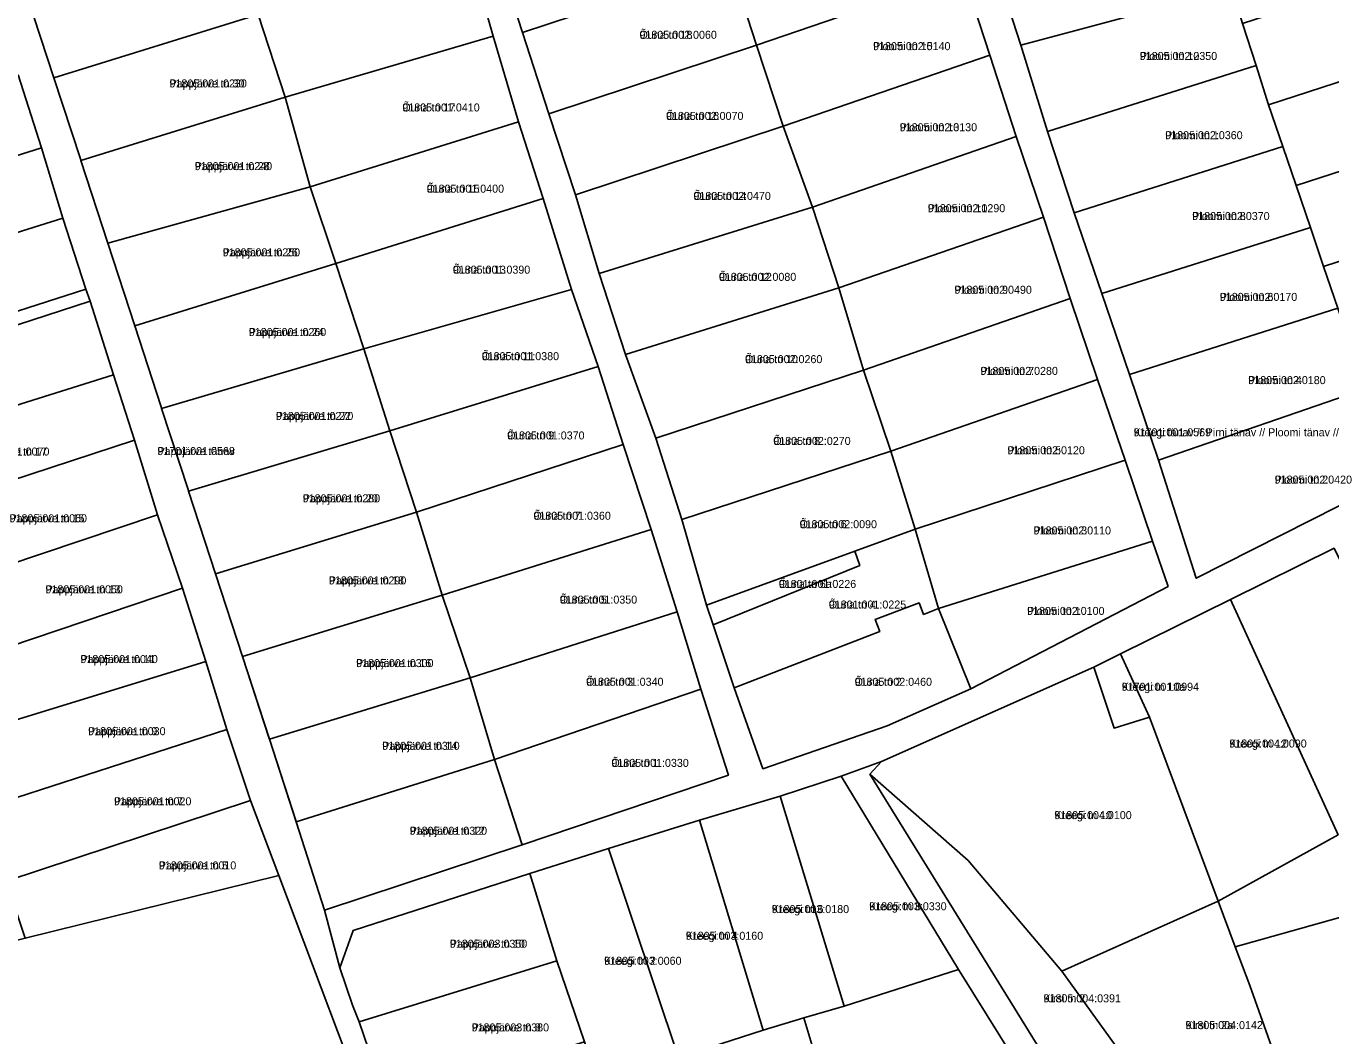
# Model space of a CAD drawing. Extents: x 655954 to 711923, y 6395079 to 6429745.
# Drawn here: x 680310.1 to 680554.7, y 6412291.4 to 6412480.8 of the extents above; entities that cross this region are included whole.
import ezdxf

# ---------------------------------------------------------------- set-up
doc = ezdxf.new("R2010")
doc.units = 0
for name, color, linetype in [('L_AADRESS', 7, 'Continuous'), ('PIIR', 7, 'Continuous'), ('TUNNUS', 7, 'Continuous')]:
    doc.layers.add(name, color=color, linetype=linetype)

msp = doc.modelspace()

# ---------------------------------------------------------------- linework, layer by layer
at = {"layer": 'PIIR'}
for points in [[(680398.24, 6412494.78), (680437.15, 6412507.67), (680441.72, 6412493.55), (680442.08, 6412492.44), (680403.17, 6412479.55)], [(680480.87, 6412505.74), (680485.79, 6412490.52), (680447.01, 6412477.21), (680442.08, 6412492.44)], [(680496.53, 6412477.2), (680491.36, 6412493.27), (680513.5, 6412500.46), (680514.14, 6412498.52), (680530.99, 6412503.84), (680533.46, 6412496.2), (680536.07, 6412487.8)], [(680348.59, 6412498.45), (680353.64, 6412482.95), (680315.35, 6412471.08), (680310.3, 6412486.58)], [(680353.64, 6412482.95), (680393.05, 6412495.15), (680397.69, 6412478.89), (680358.69, 6412467.45)], [(680403.17, 6412479.55), (680442.08, 6412492.44), (680447.01, 6412477.21), (680408.11, 6412464.32)], [(680543, 6412466), (680540.64, 6412473.35), (680538.11, 6412481.23), (680578.1, 6412494.24), (680582.92, 6412478.99)], [(680485.79, 6412490.52), (680490.73, 6412475.29), (680452.04, 6412461.99), (680447.01, 6412477.21)], [(680501.58, 6412461.01), (680496.53, 6412477.2), (680536.07, 6412487.8), (680538.11, 6412481.23), (680540.64, 6412473.35)], [(680353.64, 6412482.95), (680358.69, 6412467.45), (680320.4, 6412455.58), (680320.31, 6412455.85), (680315.35, 6412471.08)], [(680358.69, 6412467.45), (680397.69, 6412478.89), (680402.42, 6412462.83), (680363.38, 6412450.63)], [(680548.14, 6412450.85), (680545.66, 6412458.17), (680543, 6412466), (680582.92, 6412478.99), (680588.07, 6412463.84)], [(680408.11, 6412464.32), (680447.01, 6412477.21), (680452.04, 6412461.99), (680413.12, 6412449.13)], [(680490.73, 6412475.29), (680495.66, 6412460.07), (680457.49, 6412446.82), (680452.04, 6412461.99)], [(680506.55, 6412445.76), (680501.58, 6412461.01), (680540.64, 6412473.35), (680543, 6412466), (680545.66, 6412458.17)], [(680308.64, 6412471.62), (680313.01, 6412457.95), (680245.07, 6412436.41), (680240.87, 6412450.14)], [(680358.69, 6412467.45), (680363.38, 6412450.63), (680325.45, 6412440.08), (680320.4, 6412455.58)], [(680363.38, 6412450.63), (680402.42, 6412462.83), (680407.03, 6412448.42), (680368.19, 6412436.23)], [(680553.29, 6412435.7), (680550.82, 6412443.02), (680548.14, 6412450.85), (680588.07, 6412463.84), (680593.23, 6412448.68)], [(680413.12, 6412449.13), (680452.04, 6412461.99), (680457.49, 6412446.82), (680417.51, 6412434.36)], [(680313.01, 6412457.95), (680317.03, 6412444.78), (680248.37, 6412423.19), (680245.07, 6412436.41)], [(680495.66, 6412460.07), (680500.79, 6412444.91), (680462.42, 6412431.66), (680457.49, 6412446.82)], [(680511.72, 6412430.62), (680506.55, 6412445.76), (680545.66, 6412458.17), (680548.14, 6412450.85), (680550.82, 6412443.02)], [(680363.38, 6412450.63), (680368.19, 6412436.23), (680330.5, 6412424.58), (680325.45, 6412440.08)], [(680368.19, 6412436.23), (680407.03, 6412448.42), (680412.36, 6412431.39), (680373.44, 6412420.27)], [(680558.48, 6412420.56), (680555.97, 6412427.89), (680553.29, 6412435.7), (680593.23, 6412448.68), (680598.48, 6412433.57)], [(680422.47, 6412419.18), (680417.51, 6412434.36), (680457.49, 6412446.82), (680462.42, 6412431.66)], [(680317.03, 6412444.78), (680321.34, 6412431.42), (680261.14, 6412412.06), (680259.66, 6412416.51), (680250.78, 6412413.69), (680248.37, 6412423.19)], [(680505.8, 6412429.67), (680467.07, 6412416.25), (680462.42, 6412431.66), (680500.79, 6412444.91)], [(680516.89, 6412415.47), (680511.72, 6412430.62), (680550.82, 6412443.02), (680553.29, 6412435.7), (680555.97, 6412427.89)], [(680368.19, 6412436.23), (680373.44, 6412420.27), (680335.54, 6412409.08), (680335.45, 6412409.36), (680330.5, 6412424.58)], [(680322.13, 6412429.18), (680262.23, 6412409.71), (680264.29, 6412402.3), (680254.55, 6412399.61), (680250.78, 6412413.69), (680259.66, 6412416.51), (680261.14, 6412412.06), (680321.34, 6412431.42)], [(680378.32, 6412404.88), (680373.44, 6412420.27), (680412.36, 6412431.39), (680417.34, 6412416.92)], [(680422.47, 6412419.18), (680462.42, 6412431.66), (680467.07, 6412416.25), (680428.13, 6412403.48)], [(680264.29, 6412402.3), (680262.23, 6412409.71), (680322.13, 6412429.18), (680326.55, 6412415.35), (680266.62, 6412396.55)], [(680505.8, 6412429.67), (680510.93, 6412414.51), (680472.2, 6412401.06), (680467.07, 6412416.25)], [(680522.35, 6412399.39), (680516.89, 6412415.47), (680555.97, 6412427.89), (680558.48, 6412420.56), (680561.17, 6412412.73)], [(680373.44, 6412420.27), (680378.32, 6412404.88), (680340.59, 6412393.58), (680340.5, 6412393.86), (680335.54, 6412409.08)], [(680378.32, 6412404.88), (680417.34, 6412416.92), (680422.06, 6412402.33), (680383.31, 6412389.61)], [(680428.13, 6412403.48), (680467.07, 6412416.25), (680472.2, 6412401.06), (680433, 6412388.24)], [(680266.62, 6412396.55), (680326.55, 6412415.35), (680330.46, 6412403.15), (680275.58, 6412385.15)], [(680510.93, 6412414.51), (680516.09, 6412399.37), (680476.78, 6412386.46), (680472.2, 6412401.06)], [(680529.44, 6412377.25), (680522.35, 6412399.39), (680561.17, 6412412.73), (680566.82, 6412396.17)], [(680378.32, 6412404.88), (680383.31, 6412389.61), (680345.64, 6412378.08), (680340.59, 6412393.58)], [(680275.58, 6412385.15), (680330.46, 6412403.15), (680334.76, 6412389.13), (680284.72, 6412372.33)], [(680383.31, 6412389.61), (680422.06, 6412402.33), (680427.3, 6412386.4), (680388.13, 6412374.1)], [(680476.78, 6412386.46), (680465.44, 6412382.34), (680437.63, 6412372.2), (680433, 6412388.24), (680472.2, 6412401.06)], [(680516.09, 6412399.37), (680521.25, 6412384.22), (680481.14, 6412371.55), (680476.78, 6412386.46)], [(680383.31, 6412389.61), (680388.13, 6412374.1), (680350.69, 6412362.58), (680345.64, 6412378.08)], [(680284.72, 6412372.33), (680334.76, 6412389.13), (680339.43, 6412375.37), (680292.97, 6412359.71)], [(680388.13, 6412374.1), (680427.3, 6412386.4), (680432.13, 6412370.92), (680393.34, 6412358.58)], [(680465.44, 6412382.34), (680476.78, 6412386.46), (680481.14, 6412371.55), (680478.32, 6412370.45), (680477.5, 6412372.62), (680469.28, 6412369.52), (680470.13, 6412367.27), (680442.85, 6412356.68), (680438.87, 6412368.51), (680466.36, 6412379.66)], [(680437.63, 6412372.2), (680465.44, 6412382.34), (680466.36, 6412379.66), (680438.87, 6412368.51)], [(680521.25, 6412384.22), (680524.14, 6412375.7), (680487.16, 6412356.51), (680481.14, 6412371.55)], [(680556.01, 6412329.17), (680535.87, 6412373.26), (680555.27, 6412382.86), (680558.9, 6412375.47), (680562.02, 6412369.46), (680573.96, 6412339.16), (680581.04, 6412320.56), (680536.7, 6412308.12), (680533.53, 6412316.71)], [(680292.97, 6412359.71), (680339.43, 6412375.37), (680343.83, 6412361.63), (680297.31, 6412347.3)], [(680388.13, 6412374.1), (680393.34, 6412358.58), (680355.73, 6412347.08), (680355.64, 6412347.36), (680350.69, 6412362.58)], [(680471.5, 6412349.58), (680448.23, 6412341.54), (680442.85, 6412356.68), (680470.13, 6412367.27), (680469.28, 6412369.52), (680477.5, 6412372.62), (680478.32, 6412370.45), (680481.14, 6412371.55), (680487.16, 6412356.51)], [(680520.65, 6412351.23), (680515.26, 6412363.1), (680535.87, 6412373.26), (680556.01, 6412329.17), (680533.53, 6412316.71)], [(680393.34, 6412358.58), (680432.13, 6412370.92), (680436.59, 6412356.48), (680397.95, 6412343.26)], [(680520.65, 6412351.23), (680514.02, 6412349.16), (680510.24, 6412360.6), (680515.26, 6412363.1)], [(680297.31, 6412347.3), (680343.83, 6412361.63), (680347.79, 6412348.87), (680301.78, 6412334.02)], [(680486.71, 6412324.31), (680468.27, 6412340.52), (680470.47, 6412342.9), (680510.24, 6412360.6), (680514.02, 6412349.16), (680520.65, 6412351.23), (680533.53, 6412316.71), (680504.21, 6412303.58)], [(680393.34, 6412358.58), (680397.95, 6412343.26), (680360.78, 6412331.58), (680360.69, 6412331.86), (680355.73, 6412347.08)], [(680397.95, 6412343.26), (680436.59, 6412356.48), (680441.76, 6412340.34), (680403.1, 6412327.28)], [(680301.78, 6412334.02), (680347.79, 6412348.87), (680352.17, 6412335.58), (680306.39, 6412320.48)], [(680397.95, 6412343.26), (680403.1, 6412327.28), (680366.09, 6412315.05), (680360.78, 6412331.58)], [(680468.27, 6412340.52), (680486.71, 6412324.31), (680504.21, 6412303.58), (680533.37, 6412263.23), (680520.07, 6412256.74)], [(680462.89, 6412340.13), (680484.86, 6412303.92), (680463.42, 6412297.01), (680451.44, 6412336.37)], [(680306.39, 6412320.48), (680352.17, 6412335.58), (680357.48, 6412321.49), (680309.99, 6412309.75)], [(680436.31, 6412331.9), (680451.44, 6412336.37), (680463.42, 6412297.01), (680455.87, 6412294.86), (680448.28, 6412292.55)], [(680419.26, 6412326.61), (680436.31, 6412331.9), (680448.28, 6412292.55), (680432.38, 6412287.38)], [(680417.09, 6412282.78), (680414.79, 6412290.36), (680409.59, 6412305.53), (680404.56, 6412321.9), (680419.26, 6412326.61), (680432.38, 6412287.38)], [(680270.91, 6412285.97), (680269.56, 6412291.77), (680268.21, 6412300.15), (680272.04, 6412300.46), (680309.99, 6412309.75), (680357.48, 6412321.49), (680370.12, 6412288.02), (680379.49, 6412257.67), (680371.24, 6412239.08), (680328.42, 6412244.77), (680267.41, 6412253.09), (680266.95, 6412257.92), (680268.29, 6412258.95), (680268.5, 6412260.8), (680268.26, 6412264.21), (680268.94, 6412267.94), (680271.87, 6412272.08), (680272.87, 6412275.64), (680272.53, 6412278.95)], [(680368.93, 6412304.18), (680371.42, 6412311.21), (680404.56, 6412321.9), (680409.59, 6412305.53), (680372.55, 6412294.06), (680371.34, 6412297.19)], [(680618.32, 6412308.62), (680620.58, 6412307.34), (680623.03, 6412290.2), (680620.29, 6412289.89), (680608.75, 6412288.56), (680550.62, 6412269.6), (680539.47, 6412300.88), (680536.7, 6412308.12), (680581.04, 6412320.56), (680588.15, 6412306.97), (680590.63, 6412307.28)], [(680504.21, 6412303.58), (680533.53, 6412316.71), (680536.7, 6412308.12), (680539.47, 6412300.88), (680550.62, 6412269.6), (680545.58, 6412269.1), (680533.37, 6412263.23)], [(680377.69, 6412279.06), (680372.55, 6412294.06), (680409.59, 6412305.53), (680414.79, 6412290.36)], [(680498.01, 6412282.81), (680462.72, 6412272.18), (680460.59, 6412279.24), (680455.87, 6412294.86), (680463.42, 6412297.01), (680484.86, 6412303.92)], [(680420.82, 6412275.45), (680419.47, 6412275.06), (680417.09, 6412282.78), (680432.38, 6412287.38), (680448.28, 6412292.55), (680455.87, 6412294.86), (680460.59, 6412279.24), (680423.36, 6412267.88)]]:
    msp.add_lwpolyline(points, close=True, dxfattribs=at)
for points in [[(680305.26, 6412502.08), (680310.3, 6412486.58), (680315.35, 6412471.08), (680320.31, 6412455.85), (680320.4, 6412455.58), (680325.45, 6412440.08), (680330.5, 6412424.58), (680335.45, 6412409.36), (680335.54, 6412409.08), (680340.5, 6412393.86), (680340.59, 6412393.58), (680345.64, 6412378.08), (680350.69, 6412362.58), (680355.73, 6412347.08), (680360.78, 6412331.58), (680366.09, 6412315.05), (680368.93, 6412304.18), (680371.34, 6412297.19), (680372.55, 6412294.06), (680377.69, 6412279.06)], [(680555.27, 6412382.86), (680535.87, 6412373.26), (680515.26, 6412363.1), (680510.24, 6412360.6), (680470.47, 6412342.9), (680462.89, 6412340.13), (680451.44, 6412336.37), (680436.31, 6412331.9), (680419.26, 6412326.61), (680404.56, 6412321.9), (680371.42, 6412311.21), (680368.93, 6412304.18), (680366.09, 6412315.05), (680403.1, 6412327.28), (680441.76, 6412340.34), (680436.59, 6412356.48), (680432.13, 6412370.92), (680427.3, 6412386.4), (680422.06, 6412402.33), (680417.34, 6412416.92), (680412.36, 6412431.39), (680407.03, 6412448.42), (680402.42, 6412462.83), (680397.69, 6412478.89), (680393.05, 6412495.15)], [(680398.24, 6412494.78), (680403.17, 6412479.55), (680408.11, 6412464.32), (680413.12, 6412449.13), (680417.51, 6412434.36), (680422.47, 6412419.18), (680428.13, 6412403.48), (680433, 6412388.24), (680437.63, 6412372.2), (680438.87, 6412368.51), (680442.85, 6412356.68), (680448.23, 6412341.54), (680471.5, 6412349.58), (680487.16, 6412356.51), (680524.14, 6412375.7), (680521.25, 6412384.22), (680516.09, 6412399.37), (680510.93, 6412414.51), (680505.8, 6412429.67), (680500.79, 6412444.91), (680495.66, 6412460.07), (680490.73, 6412475.29), (680485.79, 6412490.52)], [(680491.36, 6412493.27), (680496.53, 6412477.2), (680501.58, 6412461.01), (680506.55, 6412445.76), (680511.72, 6412430.62), (680516.89, 6412415.47), (680522.35, 6412399.39), (680529.44, 6412377.25), (680566.82, 6412396.17)], [(680370.12, 6412288.02), (680357.48, 6412321.49), (680352.17, 6412335.58), (680347.79, 6412348.87), (680343.83, 6412361.63), (680339.43, 6412375.37), (680334.76, 6412389.13), (680330.46, 6412403.15), (680326.55, 6412415.35), (680322.13, 6412429.18), (680321.34, 6412431.42), (680317.03, 6412444.78), (680313.01, 6412457.95), (680308.64, 6412471.62)], [(680498.01, 6412282.81), (680484.86, 6412303.92), (680462.89, 6412340.13), (680470.47, 6412342.9), (680468.27, 6412340.52), (680520.07, 6412256.74)]]:
    msp.add_lwpolyline(points, dxfattribs=at)

# ---------------------------------------------------------------- texts
at = {"layer": 'L_AADRESS'}
for s, p in [('Õuna tn 18', (680425.09, 6412478.38)), ('Ploomi tn 15', (680468.87, 6412476.25)), ('Ploomi tn 12', (680518.85, 6412474.41)), ('Pappjärve tn 30', (680337.02, 6412469.26)), ('Õuna tn 17', (680380.65, 6412464.76)), ('Õuna tn 16', (680430.07, 6412463.17)), ('Ploomi tn 13', (680473.86, 6412461.05)), ('Ploomi tn 10', (680523.62, 6412459.56)), ('Pappjärve tn 28', (680341.75, 6412453.76)), ('Õuna tn 15', (680385.21, 6412449.53)), ('Õuna tn 14', (680435.2, 6412448.17)), ('Ploomi tn 11', (680479.13, 6412445.87)), ('Ploomi tn 8', (680528.68, 6412444.4)), ('Pappjärve tn 26', (680346.99, 6412437.6)), ('Õuna tn 13', (680390.12, 6412434.35)), ('Õuna tn 12', (680439.97, 6412433)), ('Ploomi tn 9', (680484.12, 6412430.58)), ('Ploomi tn 6', (680533.85, 6412429.24)), ('Pappjärve tn 24', (680351.89, 6412422.65)), ('Õuna tn 11', (680395.52, 6412418.13)), ('Õuna tn 10', (680444.86, 6412417.57)), ('Ploomi tn 7', (680489, 6412415.37)), ('Ploomi tn 4', (680539.18, 6412413.64)), ('Pappjärve tn 22', (680356.96, 6412406.92)), ('Õuna tn 9', (680400.3, 6412403.27)), ('Õuna tn 8', (680450.16, 6412402.24)), ('Kreegi tänav // Pirni tänav // Ploomi tänav // Õuna tänav', (680517.7, 6412403.86)), ('Pappjärve tn 17', (680300.02, 6412400.25)), ('Pappjärve tänav', (680334.75, 6412400.34)), ('Ploomi tn 5', (680494.05, 6412400.49)), ('Ploomi tn 2', (680544.12, 6412394.99)), ('Pappjärve tn 20', (680361.99, 6412391.48)), ('Pappjärve tn 15', (680307.05, 6412387.74)), ('Õuna tn 7', (680405.22, 6412388.21)), ('Õuna tn 6', (680455.1, 6412386.63)), ('Ploomi tn 3', (680498.95, 6412385.46)), ('Pappjärve tn 18', (680366.9, 6412376.09)), ('Õuna tn 6a', (680451.2, 6412375.43)), ('Pappjärve tn 13', (680313.78, 6412374.42)), ('Õuna tn 5', (680410.16, 6412372.49)), ('Õuna tn 4', (680460.57, 6412371.57)), ('Ploomi tn 1', (680497.74, 6412370.37)), ('Pappjärve tn 11', (680320.33, 6412361.34)), ('Pappjärve tn 16', (680372, 6412360.59)), ('Õuna tn 3', (680415.09, 6412357.09)), ('Õuna tn 2', (680465.41, 6412357.08)), ('Kreegi tn 10a', (680515.45, 6412356.15)), ('Pappjärve tn 9', (680321.78, 6412347.82)), ('Pappjärve tn 14', (680376.89, 6412345.08)), ('Kreegi tn 12', (680535.63, 6412345.51)), ('Õuna tn 1', (680419.83, 6412341.88)), ('Pappjärve tn 7', (680326.62, 6412334.68)), ('Kreegi tn 10', (680502.83, 6412332.09)), ('Pappjärve tn 12', (680382.03, 6412329.16)), ('Pappjärve tn 5', (680335.03, 6412322.66)), ('Kreegi tn 6', (680449.87, 6412314.47)), ('Kreegi tn 8', (680468.15, 6412315)), ('Kreegi tn 4', (680433.77, 6412309.47)), ('Pappjärve tn 10', (680389.56, 6412307.98)), ('Kreegi tn 2', (680418.47, 6412304.78)), ('Kirsi tn 2', (680500.82, 6412297.74)), ('Pappjärve tn 8', (680393.64, 6412292.29)), ('Kirsi tn 2a', (680527.41, 6412292.72))]:
    msp.add_text(s, height=1.5, dxfattribs=at).set_placement(p)
at = {"layer": 'TUNNUS'}
for s, p in [('91805:002:0060', (680425.09, 6412478.38)), ('91805:002:0140', (680468.87, 6412476.25)), ('91805:002:0350', (680518.85, 6412474.41)), ('91805:001:0230', (680337.02, 6412469.26)), ('91805:001:0410', (680380.65, 6412464.76)), ('91805:002:0070', (680430.07, 6412463.17)), ('91805:002:0130', (680473.86, 6412461.05)), ('91805:002:0360', (680523.62, 6412459.56)), ('91805:001:0240', (680341.75, 6412453.76)), ('91805:001:0400', (680385.21, 6412449.53)), ('91805:002:0470', (680435.2, 6412448.17)), ('91805:002:0290', (680479.13, 6412445.87)), ('91805:002:0370', (680528.68, 6412444.4)), ('91805:001:0250', (680346.99, 6412437.6)), ('91805:001:0390', (680390.12, 6412434.35)), ('91805:002:0080', (680439.97, 6412433)), ('91805:002:0490', (680484.12, 6412430.58)), ('91805:002:0170', (680533.85, 6412429.24)), ('91805:001:0260', (680351.89, 6412422.65)), ('91805:001:0380', (680395.52, 6412418.13)), ('91805:002:0260', (680444.86, 6412417.57)), ('91805:002:0280', (680489, 6412415.37)), ('91805:002:0180', (680539.18, 6412413.64)), ('91805:001:0270', (680356.96, 6412406.92)), ('91805:001:0370', (680400.3, 6412403.27)), ('91701:001:0569', (680517.7, 6412403.86)), ('91805:001:0070', (680300.02, 6412400.25)), ('91701:001:0568', (680334.75, 6412400.34)), ('91805:002:0270', (680450.16, 6412402.24)), ('91805:002:0120', (680494.05, 6412400.49)), ('91805:002:0420', (680544.12, 6412394.99)), ('91805:001:0280', (680361.99, 6412391.48)), ('91805:001:0060', (680307.05, 6412387.74)), ('91805:001:0360', (680405.22, 6412388.21)), ('91805:002:0090', (680455.1, 6412386.63)), ('91805:002:0110', (680498.95, 6412385.46)), ('91805:001:0290', (680366.9, 6412376.09)), ('91805:001:0050', (680313.78, 6412374.42)), ('91801:001:0226', (680451.2, 6412375.43)), ('91805:001:0350', (680410.16, 6412372.49)), ('91801:001:0225', (680460.57, 6412371.57)), ('91805:002:0100', (680497.74, 6412370.37)), ('91805:001:0040', (680320.33, 6412361.34)), ('91805:001:0300', (680372, 6412360.59)), ('91805:001:0340', (680415.09, 6412357.09)), ('91805:002:0460', (680465.41, 6412357.08)), ('91701:001:0994', (680515.45, 6412356.15)), ('91805:001:0030', (680321.78, 6412347.82)), ('91805:001:0310', (680376.89, 6412345.08)), ('91805:004:0090', (680535.63, 6412345.51)), ('91805:001:0330', (680419.83, 6412341.88)), ('91805:001:0020', (680326.62, 6412334.68)), ('91805:004:0100', (680502.83, 6412332.09)), ('91805:001:0320', (680382.03, 6412329.16)), ('91805:001:0010', (680335.03, 6412322.66)), ('91805:003:0180', (680449.87, 6412314.47)), ('91805:003:0330', (680468.15, 6412315)), ('91805:003:0160', (680433.77, 6412309.47)), ('91805:003:0350', (680389.56, 6412307.98)), ('91805:003:0060', (680418.47, 6412304.78)), ('91805:004:0391', (680500.82, 6412297.74)), ('91805:004:0142', (680527.41, 6412292.72)), ('91805:003:0380', (680393.64, 6412292.29))]:
    msp.add_text(s, height=1.5, dxfattribs=at).set_placement(p)

doc.saveas('drawing.dxf')
